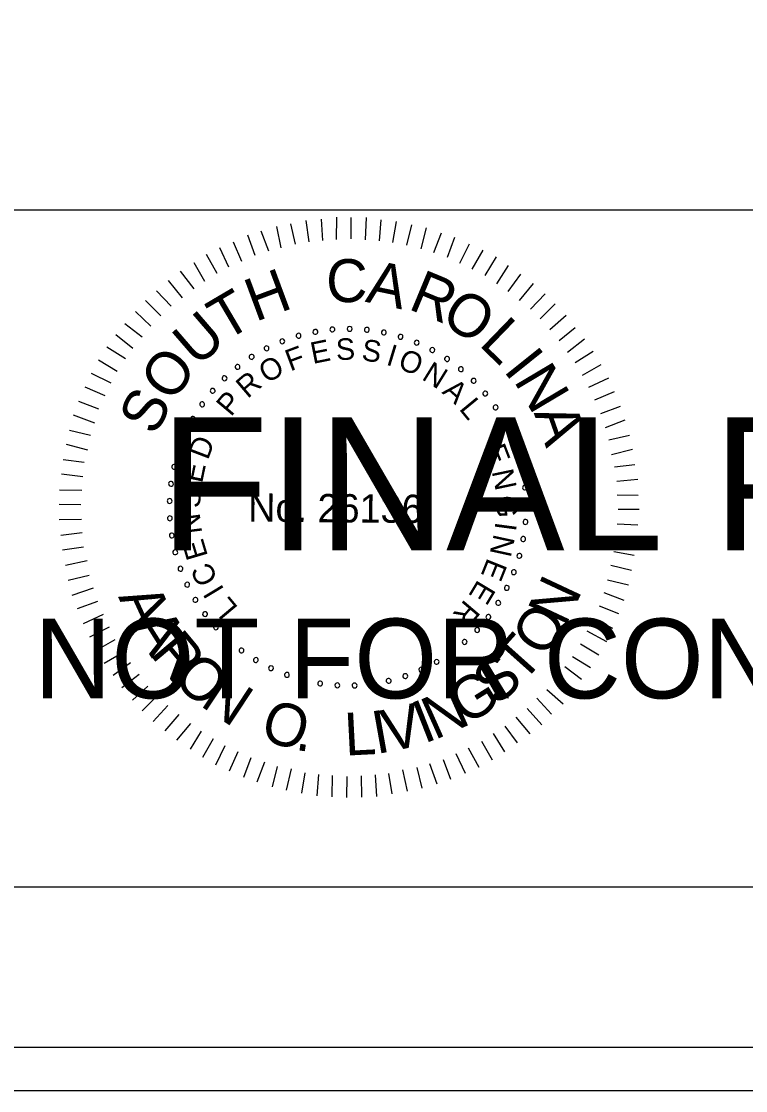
# Model space of a CAD drawing. Extents: x 967 to 1326, y 964 to 2304.
# Drawn here: x 1170.56 to 1189.3, y 1243.72 to 1271.36 of the extents above; entities that cross this region are included whole.
import ezdxf

# ---------------------------------------------------------------- set-up
doc = ezdxf.new("R2010")
doc.units = 0
for name, color, linetype in [('RD_PD_PaveShd', 7, 'Continuous'), ('RD_XS_Misc_Line', 7, 'Continuous'), ('RD_XS_PaveOvlay', 7, 'Continuous'), ('RD_XS_TX_Elev_EX', 7, 'Continuous'), ('RD_XS_TX_Elev_PR', 7, 'Continuous')]:
    doc.layers.add(name, color=color, linetype=linetype)

msp = doc.modelspace()

# ---------------------------------------------------------------- linework, layer by layer
at = {"layer": 'RD_PD_PaveShd'}
for p, q in [((996.114, 1266.486), (1323.886, 1266.486)), ((1323.886, 1248.983), (996.114, 1248.983))]:
    msp.add_line(p, q, dxfattribs=at)
at = {"layer": 'RD_XS_Misc_Line'}
for p, q in [((1178.01, 1265.663), (1177.93, 1266.209)), ((1178.364, 1265.699), (1178.33, 1266.244)), ((1178.717, 1265.719), (1178.722, 1266.295)), ((1179.093, 1265.739), (1179.098, 1266.292)), ((1179.469, 1265.713), (1179.489, 1266.288)), ((1179.829, 1265.687), (1179.872, 1266.231)), ((1180.174, 1265.646), (1180.271, 1266.19)), ((1176.964, 1265.419), (1176.769, 1265.935)), ((1177.287, 1265.508), (1177.169, 1266.054)), ((1177.657, 1265.597), (1177.53, 1266.128)), ((1180.535, 1265.573), (1180.662, 1266.102)), ((1180.902, 1265.478), (1181.045, 1266.022)), ((1176.264, 1265.156), (1176.053, 1265.657)), ((1176.61, 1265.306), (1176.423, 1265.83)), ((1181.231, 1265.384), (1181.428, 1265.896)), ((1181.584, 1265.265), (1181.78, 1265.786)), ((1175.933, 1265.005), (1175.699, 1265.506)), ((1181.905, 1265.109), (1182.154, 1265.606)), ((1182.226, 1264.953), (1182.506, 1265.45)), ((1175.308, 1264.634), (1175.036, 1265.12)), ((1175.624, 1264.846), (1175.352, 1265.332)), ((1182.562, 1264.789), (1182.85, 1265.27)), ((1175.03, 1264.445), (1174.681, 1264.9)), ((1182.86, 1264.572), (1183.163, 1265.053)), ((1183.158, 1264.378), (1183.484, 1264.828)), ((1174.729, 1264.217), (1174.372, 1264.665)), ((1183.447, 1264.145), (1183.811, 1264.587)), ((1174.435, 1263.997), (1174.062, 1264.399)), ((1183.729, 1263.92), (1184.116, 1264.316)), ((1174.172, 1263.753), (1173.776, 1264.148)), ((1183.98, 1263.672), (1184.368, 1264.061)), ((1173.909, 1263.479), (1173.52, 1263.858)), ((1184.232, 1263.394), (1184.657, 1263.767)), ((1173.684, 1263.197), (1173.242, 1263.546)), ((1184.475, 1263.108), (1184.892, 1263.45)), ((1173.451, 1262.9), (1173.009, 1263.256)), ((1184.687, 1262.807), (1185.128, 1263.156)), ((1173.257, 1262.64), (1172.776, 1262.936)), ((1173.039, 1262.312), (1172.559, 1262.6)), ((1184.885, 1262.544), (1185.355, 1262.832)), ((1185.081, 1262.213), (1185.56, 1262.493)), ((1172.883, 1262.006), (1172.379, 1262.256)), ((1185.24, 1261.904), (1185.756, 1262.145)), ((1172.727, 1261.677), (1172.215, 1261.904)), ((1185.399, 1261.573), (1185.907, 1261.791)), ((1172.571, 1261.333), (1172.051, 1261.53)), ((1185.549, 1261.226), (1186.057, 1261.414)), ((1172.461, 1260.974), (1171.91, 1261.178)), ((1185.669, 1260.865), (1186.185, 1261.06)), ((1172.351, 1260.652), (1171.807, 1260.787)), ((1185.759, 1260.541), (1186.297, 1260.667)), ((1172.286, 1260.276), (1171.727, 1260.419)), ((1185.832, 1260.165), (1186.371, 1260.298)), ((1172.191, 1259.955), (1171.647, 1260.029)), ((1185.906, 1259.842), (1186.436, 1259.906)), ((1172.15, 1259.587), (1171.598, 1259.653)), ((1185.964, 1259.473), (1186.51, 1259.53)), ((1172.124, 1259.234), (1171.548, 1259.239)), ((1185.977, 1259.12), (1186.514, 1259.115)), ((1172.105, 1258.866), (1171.545, 1258.871)), ((1185.997, 1258.751), (1186.542, 1258.747)), ((1172.118, 1258.482), (1171.542, 1258.471)), ((1185.971, 1258.368), (1186.508, 1258.348)), ((1172.138, 1258.136), (1171.585, 1258.072)), ((1185.952, 1258.022), (1186.497, 1257.949)), ((1172.173, 1257.768), (1171.627, 1257.688)), ((1185.888, 1257.655), (1186.417, 1257.566)), ((1172.262, 1257.414), (1171.701, 1257.296)), ((1185.808, 1257.302), (1186.345, 1257.175)), ((1172.321, 1257.037), (1171.774, 1256.911)), ((1185.729, 1256.926), (1186.265, 1256.792)), ((1172.425, 1256.707), (1171.871, 1256.519)), ((1185.634, 1256.597), (1186.146, 1256.401)), ((1172.53, 1256.36), (1172.007, 1256.173)), ((1185.508, 1256.253), (1186.013, 1256.057)), ((1172.681, 1256.029), (1172.165, 1255.788)), ((1172.831, 1255.705), (1172.323, 1255.441)), ((1185.352, 1255.924), (1185.857, 1255.675)), ((1185.188, 1255.603), (1185.7, 1255.33)), ((1172.982, 1255.374), (1172.497, 1255.094)), ((1185.024, 1255.274), (1185.498, 1254.987)), ((1173.194, 1255.042), (1172.709, 1254.762)), ((1184.822, 1254.946), (1185.288, 1254.658)), ((1173.384, 1254.78), (1172.936, 1254.453)), ((1184.62, 1254.687), (1185.055, 1254.353)), ((1173.612, 1254.478), (1173.164, 1254.129)), ((1184.403, 1254.389), (1184.814, 1254.033)), ((1173.832, 1254.177), (1173.437, 1253.812)), ((1184.155, 1254.092), (1184.574, 1253.72)), ((1174.091, 1253.945), (1173.689, 1253.541)), ((1183.899, 1253.864), (1184.28, 1253.454)), ((1174.35, 1253.674), (1173.97, 1253.263)), ((1183.644, 1253.597), (1184.024, 1253.18)), ((1174.64, 1253.442), (1174.275, 1253.022)), ((1174.937, 1253.209), (1174.58, 1252.782)), ((1183.358, 1253.37), (1183.715, 1252.944)), ((1175.212, 1253.014), (1174.932, 1252.549)), ((1182.764, 1252.952), (1183.059, 1252.482)), ((1183.065, 1253.141), (1183.384, 1252.709)), ((1175.525, 1252.812), (1175.245, 1252.331)), ((1182.463, 1252.755), (1182.743, 1252.269)), ((1175.83, 1252.633), (1175.588, 1252.136)), ((1176.159, 1252.477), (1175.94, 1251.98)), ((1181.8, 1252.431), (1182.041, 1251.93)), ((1182.124, 1252.581), (1182.396, 1252.08)), ((1176.503, 1252.321), (1176.307, 1251.816)), ((1176.855, 1252.211), (1176.651, 1251.69)), ((1177.177, 1252.1), (1177.05, 1251.572)), ((1181.122, 1252.175), (1181.31, 1251.652)), ((1181.476, 1252.28), (1181.664, 1251.771)), ((1177.545, 1252.036), (1177.409, 1251.484)), ((1177.897, 1251.933), (1177.808, 1251.412)), ((1178.25, 1251.892), (1178.207, 1251.34)), ((1178.603, 1251.866), (1178.598, 1251.313)), ((1178.978, 1251.84), (1178.974, 1251.295)), ((1179.355, 1251.86), (1179.365, 1251.307)), ((1179.715, 1251.88), (1179.749, 1251.327)), ((1180.061, 1251.915), (1180.149, 1251.393)), ((1180.423, 1252.012), (1180.541, 1251.458)), ((1180.791, 1252.07), (1180.926, 1251.54))]:
    msp.add_line(p, q, dxfattribs=at)
for centre, start, end in [((1178.609, 1263.397), 5.0653, 185.0653), ((1179.055, 1263.414), 359.5268, 179.5268), ((1179.055, 1263.414), 179.5268, 359.5268), ((1179.5, 1263.388), 353.9884, 173.9884), ((1177.312, 1263.091), 21.6807, 201.6807), ((1177.734, 1263.235), 16.1422, 196.1422), ((1177.734, 1263.235), 196.1422, 16.1422), ((1178.168, 1263.337), 10.6038, 190.6038), ((1178.168, 1263.337), 190.6038, 10.6038), ((1178.609, 1263.397), 185.0653, 5.0653), ((1179.5, 1263.388), 173.9884, 353.9884), ((1179.94, 1263.319), 168.4499, 348.4499), ((1179.94, 1263.319), 348.4499, 168.4499), ((1180.372, 1263.208), 162.9114, 342.9114), ((1180.372, 1263.208), 342.9114, 162.9114), ((1176.906, 1262.908), 27.2191, 207.2191), ((1176.906, 1262.908), 207.2191, 27.2191), ((1177.312, 1263.091), 201.6807, 21.6807), ((1180.79, 1263.056), 157.373, 337.373), ((1180.79, 1263.056), 337.373, 157.373), ((1181.193, 1262.864), 151.8345, 331.8345), ((1181.193, 1262.864), 331.8345, 151.8345), ((1176.52, 1262.686), 32.7576, 212.7576), ((1176.52, 1262.686), 212.7576, 32.7576), ((1181.574, 1262.634), 146.2961, 326.2961), ((1181.574, 1262.634), 326.2961, 146.2961), ((1176.156, 1262.428), 38.2961, 218.2961), ((1176.156, 1262.428), 218.2961, 38.2961), ((1181.932, 1262.368), 140.7576, 320.7576), ((1181.932, 1262.368), 320.7576, 140.7576), ((1175.82, 1262.135), 43.8345, 223.8345), ((1175.82, 1262.135), 223.8345, 43.8345), ((1182.263, 1262.069), 135.2191, 315.2191), ((1182.263, 1262.069), 315.2191, 135.2191), ((1175.513, 1261.812), 49.373, 229.373), ((1175.513, 1261.812), 229.373, 49.373), ((1182.563, 1261.74), 129.6807, 309.6807), ((1182.563, 1261.74), 309.6807, 129.6807), ((1175.239, 1261.461), 54.9114, 234.9114), ((1175.239, 1261.461), 234.9114, 54.9114), ((1182.83, 1261.383), 124.1422, 304.1422), ((1182.83, 1261.383), 304.1422, 124.1422), ((1175, 1261.085), 60.4499, 240.4499), ((1175, 1261.085), 240.4499, 60.4499), ((1183.061, 1261.002), 118.6038, 298.6038), ((1183.061, 1261.002), 298.6038, 118.6038), ((1174.798, 1260.687), 65.9884, 245.9884), ((1174.798, 1260.687), 245.9884, 65.9884), ((1183.255, 1260.601), 113.0653, 293.0653), ((1183.255, 1260.601), 293.0653, 113.0653), ((1174.636, 1260.272), 71.5268, 251.5268), ((1174.636, 1260.272), 251.5268, 71.5268), ((1183.408, 1260.182), 107.5268, 287.5268), ((1183.408, 1260.182), 287.5268, 107.5268), ((1174.514, 1259.843), 77.0653, 257.0653), ((1174.514, 1259.843), 257.0653, 77.0653), ((1183.521, 1259.751), 101.9884, 281.9884), ((1183.521, 1259.751), 281.9884, 101.9884), ((1174.435, 1259.405), 82.6038, 262.6038), ((1174.435, 1259.405), 262.6038, 82.6038), ((1183.592, 1259.311), 96.4499, 276.4499), ((1183.592, 1259.311), 276.4499, 96.4499), ((1174.398, 1258.961), 88.1422, 268.1422), ((1174.398, 1258.961), 268.1422, 88.1422), ((1183.619, 1258.866), 90.9114, 270.9114), ((1183.619, 1258.866), 270.9114, 90.9114), ((1174.404, 1258.515), 93.6807, 273.6807), ((1174.404, 1258.515), 273.6807, 93.6807), ((1183.604, 1258.421), 85.373, 265.373), ((1183.604, 1258.421), 265.373, 85.373), ((1174.453, 1258.072), 99.2191, 279.2191), ((1174.453, 1258.072), 279.2191, 99.2191), ((1183.546, 1257.979), 79.8345, 259.8345), ((1183.546, 1257.979), 259.8345, 79.8345), ((1174.545, 1257.636), 104.7576, 284.7576), ((1174.545, 1257.636), 284.7576, 104.7576), ((1183.445, 1257.545), 74.2961, 254.2961), ((1183.445, 1257.545), 254.2961, 74.2961), ((1174.678, 1257.211), 110.2961, 290.2961), ((1174.678, 1257.211), 290.2961, 110.2961), ((1183.303, 1257.122), 68.7576, 248.7576), ((1183.303, 1257.122), 248.7576, 68.7576), ((1174.852, 1256.8), 115.8345, 295.8345), ((1174.852, 1256.8), 295.8345, 115.8345), ((1183.121, 1256.716), 63.2191, 243.2191), ((1183.121, 1256.716), 243.2191, 63.2191), ((1175.065, 1256.409), 121.373, 301.373), ((1175.065, 1256.409), 301.373, 121.373), ((1182.9, 1256.328), 57.6807, 237.6807), ((1182.9, 1256.328), 237.6807, 57.6807), ((1175.314, 1256.039), 126.9114, 306.9114), ((1175.314, 1256.039), 306.9114, 126.9114), ((1182.643, 1255.964), 52.1422, 232.1422), ((1182.643, 1255.964), 232.1422, 52.1422), ((1175.598, 1255.696), 132.4499, 312.4499), ((1175.598, 1255.696), 312.4499, 132.4499), ((1182.353, 1255.627), 46.6038, 226.6038), ((1175.914, 1255.381), 137.9884, 317.9884), ((1175.914, 1255.381), 317.9884, 137.9884), ((1182.353, 1255.627), 226.6038, 46.6038), ((1176.258, 1255.099), 143.5268, 323.5268), ((1176.258, 1255.099), 323.5268, 143.5268), ((1182.03, 1255.319), 41.0653, 221.0653), ((1182.03, 1255.319), 221.0653, 41.0653), ((1176.629, 1254.851), 149.0653, 329.0653), ((1176.629, 1254.851), 329.0653, 149.0653), ((1181.305, 1254.803), 29.9884, 209.9884), ((1181.68, 1255.043), 35.5268, 215.5268), ((1181.68, 1255.043), 215.5268, 35.5268), ((1177.021, 1254.639), 154.6038, 334.6038), ((1177.021, 1254.639), 334.6038, 154.6038), ((1180.908, 1254.6), 24.4499, 204.4499), ((1180.908, 1254.6), 204.4499, 24.4499), ((1181.305, 1254.803), 209.9884, 29.9884), ((1177.432, 1254.467), 160.1422, 340.1422), ((1177.432, 1254.467), 340.1422, 160.1422), ((1177.858, 1254.335), 165.6807, 345.6807), ((1177.858, 1254.335), 345.6807, 165.6807), ((1178.294, 1254.245), 351.2191, 171.2191), ((1179.627, 1254.232), 7.8345, 187.8345), ((1180.065, 1254.313), 13.373, 193.373), ((1180.065, 1254.313), 193.373, 13.373), ((1180.494, 1254.436), 18.9114, 198.9114), ((1180.494, 1254.436), 198.9114, 18.9114), ((1178.294, 1254.245), 171.2191, 351.2191), ((1178.737, 1254.198), 356.7576, 176.7576), ((1178.737, 1254.198), 176.7576, 356.7576), ((1179.183, 1254.193), 2.2961, 182.2961), ((1179.183, 1254.193), 182.2961, 2.2961), ((1179.627, 1254.232), 187.8345, 7.8345)]:
    msp.add_arc(centre, 0.0627, start, end, dxfattribs=at)
at = {"layer": 'RD_XS_PaveOvlay'}
msp.add_lwpolyline([(967.409, 1243.72), (1326.285, 1243.72), (1326.285, 1463.72), (967.409, 1463.72)], close=True, dxfattribs=at)
at = {"layer": 'RD_XS_TX_Elev_EX'}
for points in [[(967.409, 1243.72), (1326.285, 1243.72), (1326.285, 1463.72), (967.409, 1463.72)], [(988.525, 1244.84), (1326.285, 1244.84), (1326.285, 1462.6), (988.525, 1462.6)]]:
    msp.add_lwpolyline(points, close=True, dxfattribs=at)

# ---------------------------------------------------------------- texts
at = {"layer": 'RD_XS_Misc_Line'}
for s, height, rotation, p in [('C', 1.11, 359.5482, (1178.442, 1264.108)), ('A', 1.11, 348.1981, (1179.439, 1264.115)), ('H', 1.11, 20.3637, (1176.614, 1263.587)), ('R', 1.11, 337.4344, (1180.541, 1263.937)), ('T', 1.11, 30.4992, (1175.828, 1263.072)), ('O', 1.108, 326.5869, (1181.366, 1263.609)), ('U', 1.11, 40.8022, (1175.102, 1262.403)), ('L', 1.11, 315.9488, (1182.373, 1263.003)), ('E', 0.557, 11.4103, (1178.103, 1262.503)), ('S', 0.557, 2.208, (1178.709, 1262.601)), ('S', 0.557, 352.6608, (1179.346, 1262.599)), ('F', 0.557, 20.6127, (1177.52, 1262.309)), ('I', 0.557, 343.1136, (1179.975, 1262.491)), ('O', 0.557, 338.4392, (1180.274, 1262.401)), ('I', 1.11, 308.6613, (1183.011, 1262.338)), ('O', 1.11, 52.0267, (1174.435, 1261.474)), ('O', 0.557, 30.8477, (1176.917, 1261.987)), ('N', 0.557, 328.2042, (1180.896, 1262.12)), ('N', 1.11, 300.7037, (1183.285, 1262.075)), ('R', 0.557, 40.3949, (1176.415, 1261.594)), ('A', 0.557, 318.657, (1181.424, 1261.762)), ('S', 1.108, 63.2511, (1174.029, 1260.619)), ('P', 0.557, 49.9421, (1175.985, 1261.124)), ('L', 0.557, 309.4546, (1181.869, 1261.339)), ('A', 1.11, 289.4792, (1183.814, 1261.243)), ('D', 0.557, 69.0364, (1175.386, 1260.003)), ('E', 0.557, 291.049, (1182.53, 1260.307)), ('E', 0.557, 78.2388, (1175.238, 1259.407)), ('N', 0.557, 281.8466, (1182.728, 1259.726)), ('S', 0.557, 87.786, (1175.187, 1258.772)), ('No. 26136', 0.7311, 359.5268, (1176.429, 1258.43)), ('G', 0.557, 272.2995, (1182.833, 1259.097)), ('N', 0.557, 97.3332, (1175.242, 1258.137)), ('I', 0.557, 262.4084, (1182.83, 1258.437)), ('E', 0.557, 106.5355, (1175.394, 1257.541)), ('N', 0.557, 257.7339, (1182.789, 1258.127)), ('C', 0.557, 116.4266, (1175.661, 1256.938)), ('E', 0.557, 248.1867, (1182.628, 1257.511)), ('I', 0.557, 121.1011, (1175.823, 1256.67)), ('E', 0.557, 238.9844, (1182.378, 1256.949)), ('N', 1.105, 64.8922, (1184.632, 1255.684)), ('A', 1.105, 294.7297, (1173.062, 1256.486)), ('L', 0.557, 129.9595, (1176.187, 1256.204)), ('R', 0.557, 229.782, (1182.041, 1256.435)), ('A', 1.105, 302.2892, (1173.414, 1255.72)), ('O', 1.105, 56.2059, (1184.102, 1254.874)), ('R', 1.105, 309.8487, (1173.865, 1255.007)), ('T', 1.105, 48.2685, (1183.515, 1254.211)), ('O', 1.105, 317.7861, (1174.434, 1254.33)), ('S', 1.105, 40.3311, (1182.842, 1253.636)), ('N', 1.105, 326.4725, (1175.158, 1253.686)), ('G', 1.105, 32.0198, (1182.059, 1253.14)), ('N', 1.105, 24.0824, (1181.252, 1252.776)), ('O', 1.105, 342.3472, (1176.697, 1252.82)), ('V', 1.105, 12.7741, (1180.033, 1252.457)), ('I', 1.105, 21.4605, (1180.976, 1252.681)), ('L', 1.105, 2.9677, (1178.943, 1252.379)), ('I', 1.105, 10.1523, (1179.743, 1252.418)), ('.', 1.105, 351.0336, (1177.623, 1252.536))]:
    msp.add_text(s, height=height, rotation=rotation, dxfattribs=at).set_placement(p)
at = {"layer": 'RD_XS_TX_Elev_PR'}
for s, height, p in [('FINAL PLANS', 3.4375, (1174.145, 1257.685)), ('NOT FOR CONSTRUCTION', 2.0625, (1170.901, 1253.86))]:
    msp.add_text(s, height=height, dxfattribs=at).set_placement(p)

doc.saveas('drawing.dxf')
